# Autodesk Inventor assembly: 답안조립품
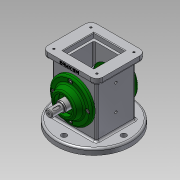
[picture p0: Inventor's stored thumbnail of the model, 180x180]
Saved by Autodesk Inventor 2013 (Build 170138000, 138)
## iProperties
Created: 2018-10
Part Number: 답안조립품
Document SubType Name: Assembly
Designer: hana-cad36
Author: hana-cad36
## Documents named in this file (7)
- C:\Documents and Settings\hana-cad36\바탕 화면\481007V1039\답안조립품.iam
- C:\Documents and Settings\hana-cad36\바탕 화면\481007V1039\본체.ipt
- C:\Documents and Settings\hana-cad36\바탕 화면\481007V1039\베어링 17 x 40 x 12.ipt
- C:\Documents and Settings\hana-cad36\바탕 화면\481007V1039\앞커버.ipt
- C:\Documents and Settings\hana-cad36\바탕 화면\481007V1039\뒤커버.ipt
- C:\Documents and Settings\hana-cad36\바탕 화면\481007V1039\편심축.ipt
- C:\Documents and Settings\hana-cad36\바탕 화면\481007V1039\볼트 M4 x 8.ipt
